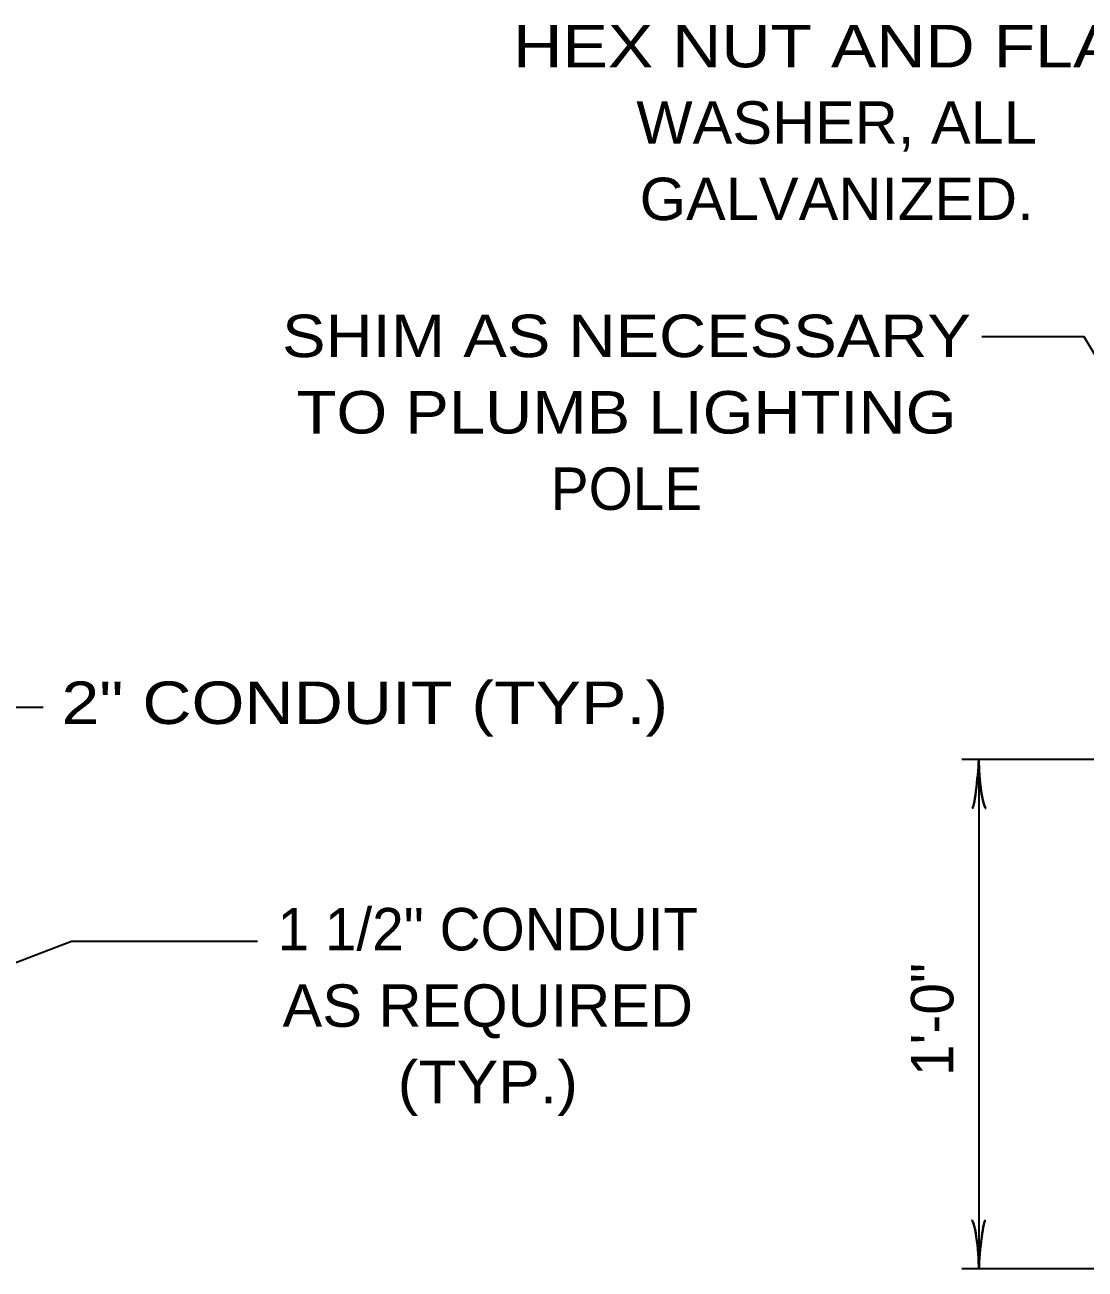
# Model space of a CAD drawing. Extents: x -1 to 679, y 0 to 440.
# Drawn here: x 213.6 to 276.1, y 99.1 to 172.3 of the extents above; entities that cross this region are included whole.
import ezdxf
from ezdxf.enums import TextEntityAlignment as Align

# ---------------------------------------------------------------- set-up
doc = ezdxf.new("R2010")
doc.units = 0
doc.layers.add('1', color=7, linetype='Continuous', lineweight=35)

msp = doc.modelspace()

# ---------------------------------------------------------------- linework, layer by layer
at = {"layer": '1'}
for p, q in [((305.854, 129.063), (268.854, 129.063)), ((269.854, 129.063), (269.854, 99.063)), ((305.854, 99.063), (268.854, 99.063))]:
    msp.add_line(p, q, dxfattribs=at)
for points in [[(283.87, 140.936), (276.055, 153.966), (270.027, 153.966)], [(195.099, 121.261), (199.457, 132.158), (214.729, 132.158)], [(201.699, 112.761), (216.389, 118.375), (227.345, 118.375)]]:
    msp.add_lwpolyline(points, dxfattribs=at)
at = {"layer": '1', "lineweight": 40}
for centre, major_axis, ratio, start_param, end_param in [((269.643, 127.943), (0.176, 1.756), 0.07063, 3.140715, 5.41811), ((270.13, 127.972), (-0.156, 1.786), 0.122415, 0.896353, 3.141593), ((269.578, 100.155), (0.156, -1.786), 0.122415, 0.896353, 3.141593), ((270.066, 100.184), (-0.176, -1.756), 0.07063, 3.140715, 5.41811)]:
    msp.add_ellipse(centre, major_axis=major_axis, ratio=ratio, start_param=start_param, end_param=end_param, dxfattribs=at)

# ---------------------------------------------------------------- texts
at = {"layer": '1'}
for s, width, p in [('HEX NUT AND FLAT', 1.2, (261.477, 169.836)), ('WASHER, ALL', 1.05, (261.477, 165.336)), ('GALVANIZED.', 1.05, (261.477, 160.836)), ('SHIM AS NECESSARY', 1.15, (249.093, 152.769)), ('TO PLUMB LIGHTING', 1.15, (249.093, 148.269)), ('AS REQUIRED', 1.05, (240.921, 113.325)), ('(TYP.)', 1.1, (240.921, 108.825))]:
    msp.add_text(s, height=2.5, dxfattribs=dict(at, width=width)).set_placement(p, align=Align.CENTER)
for s, p in [('POLE', (249.093, 143.769)), ('1 1/2" CONDUIT', (240.921, 117.825))]:
    msp.add_text(s, height=2.5, dxfattribs=at).set_placement(p, align=Align.CENTER)
at = {"layer": '1', "width": 1.2}
msp.add_text('2" CONDUIT (TYP.)', height=2.5, dxfattribs=at).set_placement((215.797, 131.162))
at = {"layer": '1'}
msp.add_text('1\'-0"', height=2.5, rotation=90, dxfattribs=at).set_placement((268.356, 110.43))

doc.saveas('drawing.dxf')
